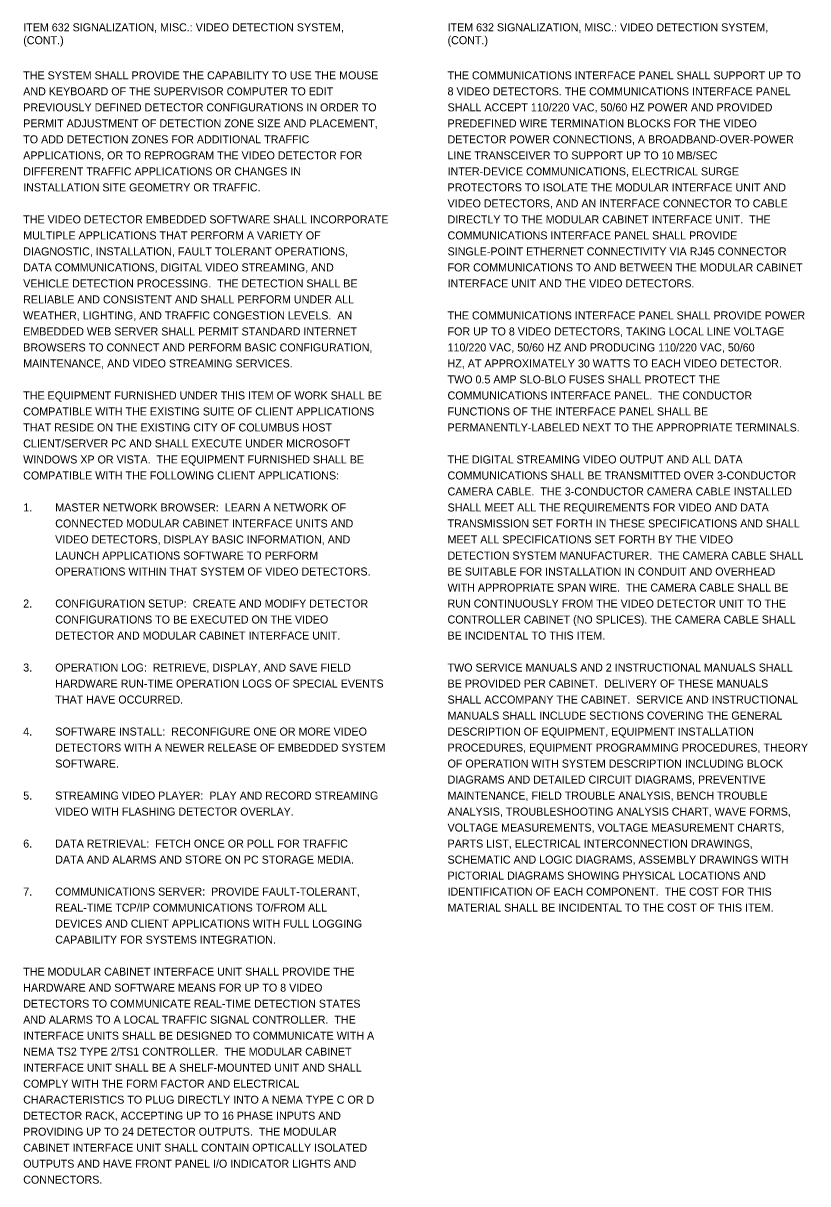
# Model space of a CAD drawing. Extents: x -38 to 65, y -51 to 25.
# Drawn here: x 8.08 to 21.8, y -50.83 to -30.52 of the extents above; entities that cross this region are included whole.
import ezdxf

# ---------------------------------------------------------------- set-up
doc = ezdxf.new("R2010")
doc.units = 0
doc.layers.add('SH_Data', color=7, linetype='Continuous')
doc.layers.add('SH_Text', color=7, linetype='Continuous')

msp = doc.modelspace()

# ---------------------------------------------------------------- texts
at = {"layer": 'SH_Data'}
for s, p in [('ITEM 632 SIGNALIZATION, MISC.: VIDEO DETECTION SYSTEM, ', (8.082, -30.667)), ('ITEM 632 SIGNALIZATION, MISC.: VIDEO DETECTION SYSTEM, ', (15.502, -30.667)), ('(CONT.)', (8.082, -30.892)), ('(CONT.)', (15.502, -30.892))]:
    msp.add_text(s, height=0.14, rotation=360, dxfattribs=at).set_placement(p)
at = {"layer": 'SH_Text'}
for s, p in [('THE SYSTEM SHALL PROVIDE THE CAPABILITY TO USE THE MOUSE ', (8.082, -31.507)), ('THE COMMUNICATIONS INTERFACE PANEL SHALL SUPPORT UP TO ', (15.502, -31.507)), ('AND KEYBOARD OF THE SUPERVISOR COMPUTER TO EDIT ', (8.082, -31.787)), ('8 VIDEO DETECTORS. THE COMMUNICATIONS INTERFACE PANEL ', (15.502, -31.787)), ('PREVIOUSLY DEFINED DETECTOR CONFIGURATIONS IN ORDER TO ', (8.082, -32.067)), ('SHALL ACCEPT 110/220 VAC, 50/60 HZ POWER AND PROVIDED ', (15.502, -32.067)), ('PERMIT ADJUSTMENT OF DETECTION ZONE SIZE AND PLACEMENT, ', (8.082, -32.347)), ('PREDEFINED WIRE TERMINATION BLOCKS FOR THE VIDEO ', (15.502, -32.347)), ('TO ADD DETECTION ZONES FOR ADDITIONAL TRAFFIC ', (8.082, -32.627)), ('DETECTOR POWER CONNECTIONS, A BROADBAND-OVER-POWER ', (15.502, -32.627)), ('APPLICATIONS, OR TO REPROGRAM THE VIDEO DETECTOR FOR ', (8.082, -32.907)), ('LINE TRANSCEIVER TO SUPPORT UP TO 10 MB/SEC ', (15.502, -32.907)), ('DIFFERENT TRAFFIC APPLICATIONS OR CHANGES IN ', (8.082, -33.187)), ('INTER-DEVICE COMMUNICATIONS, ELECTRICAL SURGE ', (15.502, -33.187)), ('INSTALLATION SITE GEOMETRY OR TRAFFIC.', (8.082, -33.467)), ('PROTECTORS TO ISOLATE THE MODULAR INTERFACE UNIT AND ', (15.502, -33.467)), ('VIDEO DETECTORS, AND AN INTERFACE CONNECTOR TO CABLE ', (15.502, -33.747)), ('THE VIDEO DETECTOR EMBEDDED SOFTWARE SHALL INCORPORATE ', (8.082, -34.027)), ('DIRECTLY TO THE MODULAR CABINET INTERFACE UNIT.  THE ', (15.502, -34.027)), ('MULTIPLE APPLICATIONS THAT PERFORM A VARIETY OF ', (8.082, -34.307)), ('COMMUNICATIONS INTERFACE PANEL SHALL PROVIDE ', (15.502, -34.307)), ('DIAGNOSTIC, INSTALLATION, FAULT TOLERANT OPERATIONS, ', (8.082, -34.587)), ('SINGLE-POINT ETHERNET CONNECTIVITY VIA RJ45 CONNECTOR ', (15.502, -34.587)), ('DATA COMMUNICATIONS, DIGITAL VIDEO STREAMING, AND ', (8.082, -34.867)), ('FOR COMMUNICATIONS TO AND BETWEEN THE MODULAR CABINET ', (15.502, -34.867)), ('VEHICLE DETECTION PROCESSING.  THE DETECTION SHALL BE ', (8.082, -35.147)), ('INTERFACE UNIT AND THE VIDEO DETECTORS.', (15.502, -35.147)), ('RELIABLE AND CONSISTENT AND SHALL PERFORM UNDER ALL ', (8.082, -35.427)), ('WEATHER, LIGHTING, AND TRAFFIC CONGESTION LEVELS.  AN ', (8.082, -35.707)), ('THE COMMUNICATIONS INTERFACE PANEL SHALL PROVIDE POWER ', (15.502, -35.707)), ('EMBEDDED WEB SERVER SHALL PERMIT STANDARD INTERNET ', (8.082, -35.987)), ('FOR UP TO 8 VIDEO DETECTORS, TAKING LOCAL LINE VOLTAGE ', (15.502, -35.987)), ('BROWSERS TO CONNECT AND PERFORM BASIC CONFIGURATION, ', (8.082, -36.267)), ('110/220 VAC, 50/60 HZ AND PRODUCING 110/220 VAC, 50/60 ', (15.502, -36.267)), ('MAINTENANCE, AND VIDEO STREAMING SERVICES.', (8.082, -36.547)), ('HZ, AT APPROXIMATELY 30 WATTS TO EACH VIDEO DETECTOR.  ', (15.502, -36.547)), ('TWO 0.5 AMP SLO-BLO FUSES SHALL PROTECT THE ', (15.502, -36.827)), ('THE EQUIPMENT FURNISHED UNDER THIS ITEM OF WORK SHALL BE ', (8.082, -37.107)), ('COMMUNICATIONS INTERFACE PANEL.  THE CONDUCTOR ', (15.502, -37.107)), ('COMPATIBLE WITH THE EXISTING SUITE OF CLIENT APPLICATIONS ', (8.082, -37.387)), ('FUNCTIONS OF THE INTERFACE PANEL SHALL BE ', (15.502, -37.387)), ('THAT RESIDE ON THE EXISTING CITY OF COLUMBUS HOST ', (8.082, -37.667)), ('PERMANENTLY-LABELED NEXT TO THE APPROPRIATE TERMINALS.', (15.502, -37.667)), ('CLIENT/SERVER PC AND SHALL EXECUTE UNDER MICROSOFT ', (8.082, -37.947)), ('WINDOWS XP OR VISTA.  THE EQUIPMENT FURNISHED SHALL BE ', (8.082, -38.227)), ('THE DIGITAL STREAMING VIDEO OUTPUT AND ALL DATA ', (15.502, -38.227)), ('COMPATIBLE WITH THE FOLLOWING CLIENT APPLICATIONS:', (8.082, -38.507)), ('COMMUNICATIONS SHALL BE TRANSMITTED OVER 3-CONDUCTOR ', (15.502, -38.507)), ('CAMERA CABLE.  THE 3-CONDUCTOR CAMERA CABLE INSTALLED ', (15.502, -38.787)), ('1.', (8.082, -39.067)), ('MASTER NETWORK BROWSER:  LEARN A NETWORK OF ', (8.642, -39.067)), ('SHALL MEET ALL THE REQUIREMENTS FOR VIDEO AND DATA ', (15.502, -39.067)), ('CONNECTED MODULAR CABINET INTERFACE UNITS AND ', (8.642, -39.347)), ('TRANSMISSION SET FORTH IN THESE SPECIFICATIONS AND SHALL ', (15.502, -39.347)), ('VIDEO DETECTORS, DISPLAY BASIC INFORMATION, AND ', (8.642, -39.627)), ('MEET ALL SPECIFICATIONS SET FORTH BY THE VIDEO ', (15.502, -39.627)), ('LAUNCH APPLICATIONS SOFTWARE TO PERFORM ', (8.642, -39.907)), ('DETECTION SYSTEM MANUFACTURER.  THE CAMERA CABLE SHALL ', (15.502, -39.907)), ('OPERATIONS WITHIN THAT SYSTEM OF VIDEO DETECTORS.', (8.642, -40.187)), ('BE SUITABLE FOR INSTALLATION IN CONDUIT AND OVERHEAD ', (15.502, -40.187)), ('WITH APPROPRIATE SPAN WIRE.  THE CAMERA CABLE SHALL BE ', (15.502, -40.467)), ('2.', (8.082, -40.747)), ('CONFIGURATION SETUP:  CREATE AND MODIFY DETECTOR ', (8.642, -40.747)), ('RUN CONTINUOUSLY FROM THE VIDEO DETECTOR UNIT TO THE ', (15.502, -40.747)), ('CONFIGURATIONS TO BE EXECUTED ON THE VIDEO ', (8.642, -41.027)), ('CONTROLLER CABINET (NO SPLICES). THE CAMERA CABLE SHALL ', (15.502, -41.027)), ('DETECTOR AND MODULAR CABINET INTERFACE UNIT.', (8.642, -41.307)), ('BE INCIDENTAL TO THIS ITEM.', (15.502, -41.307)), ('3.', (8.082, -41.867)), ('OPERATION LOG:  RETRIEVE, DISPLAY, AND SAVE FIELD ', (8.642, -41.867)), ('TWO SERVICE MANUALS AND 2 INSTRUCTIONAL MANUALS SHALL ', (15.502, -41.867)), ('HARDWARE RUN-TIME OPERATION LOGS OF SPECIAL EVENTS ', (8.642, -42.147)), ('BE PROVIDED PER CABINET.  DELIVERY OF THESE MANUALS ', (15.502, -42.147)), ('THAT HAVE OCCURRED.', (8.642, -42.427)), ('SHALL ACCOMPANY THE CABINET.  SERVICE AND INSTRUCTIONAL ', (15.502, -42.427)), ('MANUALS SHALL INCLUDE SECTIONS COVERING THE GENERAL ', (15.502, -42.707)), ('4.', (8.082, -42.987)), ('SOFTWARE INSTALL:  RECONFIGURE ONE OR MORE VIDEO ', (8.642, -42.987)), ('DESCRIPTION OF EQUIPMENT, EQUIPMENT INSTALLATION ', (15.502, -42.987)), ('DETECTORS WITH A NEWER RELEASE OF EMBEDDED SYSTEM ', (8.642, -43.267)), ('PROCEDURES, EQUIPMENT PROGRAMMING PROCEDURES, THEORY ', (15.502, -43.267)), ('SOFTWARE.', (8.642, -43.547)), ('OF OPERATION WITH SYSTEM DESCRIPTION INCLUDING BLOCK ', (15.502, -43.547)), ('DIAGRAMS AND DETAILED CIRCUIT DIAGRAMS, PREVENTIVE ', (15.502, -43.827)), ('5.', (8.082, -44.107)), ('STREAMING VIDEO PLAYER:  PLAY AND RECORD STREAMING ', (8.642, -44.107)), ('MAINTENANCE, FIELD TROUBLE ANALYSIS, BENCH TROUBLE ', (15.502, -44.107)), ('VIDEO WITH FLASHING DETECTOR OVERLAY.', (8.642, -44.387)), ('ANALYSIS, TROUBLESHOOTING ANALYSIS CHART, WAVE FORMS, ', (15.502, -44.387)), ('VOLTAGE MEASUREMENTS, VOLTAGE MEASUREMENT CHARTS, ', (15.502, -44.667)), ('6.', (8.082, -44.947)), ('DATA RETRIEVAL:  FETCH ONCE OR POLL FOR TRAFFIC ', (8.642, -44.947)), ('PARTS LIST, ELECTRICAL INTERCONNECTION DRAWINGS, ', (15.502, -44.947)), ('DATA AND ALARMS AND STORE ON PC STORAGE MEDIA.', (8.642, -45.227)), ('SCHEMATIC AND LOGIC DIAGRAMS, ASSEMBLY DRAWINGS WITH ', (15.502, -45.227)), ('PICTORIAL DIAGRAMS SHOWING PHYSICAL LOCATIONS AND ', (15.502, -45.507)), ('7.', (8.082, -45.787)), ('COMMUNICATIONS SERVER:  PROVIDE FAULT-TOLERANT, ', (8.642, -45.787)), ('IDENTIFICATION OF EACH COMPONENT.  THE COST FOR THIS ', (15.502, -45.787)), ('REAL-TIME TCP/IP COMMUNICATIONS TO/FROM ALL ', (8.642, -46.067)), ('MATERIAL SHALL BE INCIDENTAL TO THE COST OF THIS ITEM.', (15.502, -46.067)), ('DEVICES AND CLIENT APPLICATIONS WITH FULL LOGGING ', (8.642, -46.347)), ('CAPABILITY FOR SYSTEMS INTEGRATION.', (8.642, -46.627)), ('THE MODULAR CABINET INTERFACE UNIT SHALL PROVIDE THE ', (8.082, -47.187)), ('HARDWARE AND SOFTWARE MEANS FOR UP TO 8 VIDEO ', (8.082, -47.467)), ('DETECTORS TO COMMUNICATE REAL-TIME DETECTION STATES ', (8.082, -47.747)), ('AND ALARMS TO A LOCAL TRAFFIC SIGNAL CONTROLLER.  THE ', (8.082, -48.027)), ('INTERFACE UNITS SHALL BE DESIGNED TO COMMUNICATE WITH A ', (8.082, -48.307)), ('NEMA TS2 TYPE 2/TS1 CONTROLLER.  THE MODULAR CABINET ', (8.082, -48.587)), ('INTERFACE UNIT SHALL BE A SHELF-MOUNTED UNIT AND SHALL ', (8.082, -48.867)), ('COMPLY WITH THE FORM FACTOR AND ELECTRICAL ', (8.082, -49.147)), ('CHARACTERISTICS TO PLUG DIRECTLY INTO A NEMA TYPE C OR D ', (8.082, -49.427)), ('DETECTOR RACK, ACCEPTING UP TO 16 PHASE INPUTS AND ', (8.082, -49.707)), ('PROVIDING UP TO 24 DETECTOR OUTPUTS.  THE MODULAR ', (8.082, -49.987)), ('CABINET INTERFACE UNIT SHALL CONTAIN OPTICALLY ISOLATED ', (8.082, -50.267)), ('OUTPUTS AND HAVE FRONT PANEL I/O INDICATOR LIGHTS AND ', (8.082, -50.547)), ('CONNECTORS.', (8.082, -50.827))]:
    msp.add_text(s, height=0.14, rotation=360, dxfattribs=at).set_placement(p)

doc.saveas('drawing.dxf')
